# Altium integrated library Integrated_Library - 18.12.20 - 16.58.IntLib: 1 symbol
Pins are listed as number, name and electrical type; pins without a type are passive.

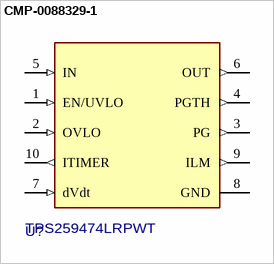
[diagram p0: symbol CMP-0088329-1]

## CMP-0088329-1
designator U?, comment TPS259474LRPWT
2.7- 23V, 5.5 A, 28 mΩ Reverse Current Blocking eFuse with Input Reverse Polarity Protection; Manufacturer: Texas Instruments; AEC Qualified: No; Nominal Supply Current: 0.5-6A; Threshold Voltage: 1.2/1.1V; Standoff Height: 0mm; Number Of Rails Monitored: 1; SizeZ_mm: 1mm; Min Supply Voltage: 2.7V; Reset Type: Active Low; TJmax_C: +125°C; Output Voltage: 42V
footprint RPW0010A-MFG
pins: 1 EN/UVLO (in), 2 OVLO (in), 3 PG (out), 4 PGTH (out), 5 IN (in), 6 OUT (out), 7 dVdt (in), 8 GND (power), 9 ILM (out), 10 ITIMER (out)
